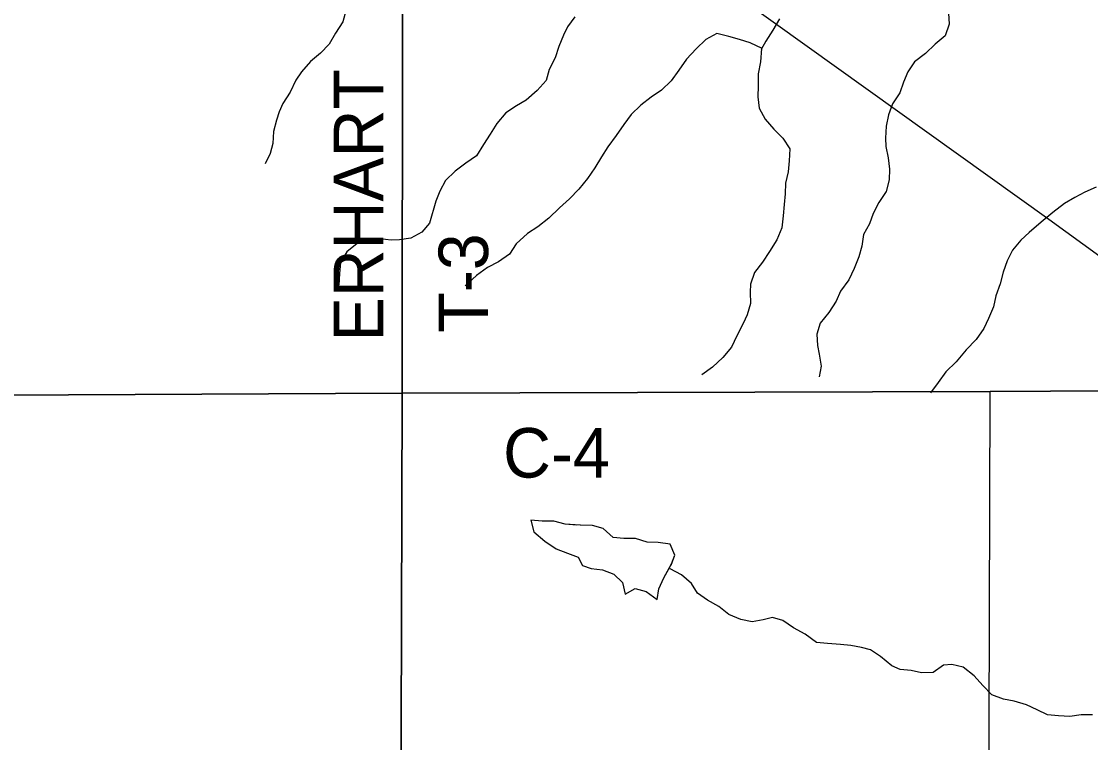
# Model space of a CAD drawing. Extents: x 1985906 to 2277390, y 930619 to 1324581.
# Drawn here: x 2110785 to 2117262, y 1140660 to 1145029 of the extents above; entities that cross this region are included whole.
import ezdxf

# ---------------------------------------------------------------- set-up
doc = ezdxf.new("R2010")
doc.units = 0
for name, color, linetype in [('GM_X_County_Road', 7, 'Continuous'), ('GM_X_County_Road_Text', 7, 'Continuous'), ('GM_X_Minor_Lake', 7, 'Continuous'), ('GM_X_Minor_River', 7, 'Continuous'), ('GM_X_Rail_Line', 7, 'Continuous'), ('GM_X_Township', 7, 'Continuous'), ('GM_X_Township_Road', 7, 'Continuous'), ('GM_X_Township_Road_Text', 7, 'Continuous')]:
    doc.layers.add(name, color=color, linetype=linetype)

msp = doc.modelspace()

# ---------------------------------------------------------------- linework, layer by layer
at = {"layer": 'GM_X_County_Road'}
for points in [[(2113092.4, 1142777.3), (2116654.7, 1142786.9), (2118848.5, 1142799.2), (2120259.1, 1142805.3), (2123319.4, 1142839.1), (2124184.9, 1142847.2)], [(2099759.2, 1142764.8), (2105186.3, 1142764.6), (2105809.5, 1142741.5), (2113092.4, 1142777.3)], [(2113088.8, 1134094.7), (2113074.8, 1137306), (2113092.4, 1142777.3)]]:
    msp.add_lwpolyline(points, dxfattribs=at)
at = {"layer": 'GM_X_Minor_Lake'}
for points in [[(2114170.4, 1141976.6), (2114080, 1141984.3), (2114011.7, 1142002.1), (2113939.5, 1142001.9), (2113871.2, 1142007.7), (2113889.6, 1141937.4), (2113956.1, 1141881.4), (2114024.5, 1141833.4), (2114092.8, 1141807.6), (2114157.2, 1141783.7), (2114183.5, 1141733.6), (2114237.7, 1141715.7), (2114306, 1141707.9), (2114374.3, 1141680), (2114426.7, 1141629.9), (2114443.1, 1141559.7), (2114503.1, 1141594), (2114569.4, 1141576.2), (2114635.9, 1141528.2), (2114647.6, 1141592.5), (2114677.4, 1141658.9), (2114724.1, 1141743.4)], [(2114148.3, 1141978.5), (2114080, 1141984.3), (2114011.7, 1142002.1), (2113939.5, 1142001.9), (2113871.2, 1142007.7), (2113889.6, 1141937.4), (2113956.1, 1141881.4), (2114024.5, 1141833.4), (2114092.8, 1141807.6), (2114157.2, 1141783.7), (2114183.5, 1141733.6), (2114237.7, 1141715.7), (2114306, 1141707.9), (2114374.3, 1141680), (2114426.7, 1141629.9), (2114443.1, 1141559.7), (2114503.1, 1141594), (2114569.4, 1141576.2), (2114635.9, 1141528.2), (2114647.6, 1141592.5), (2114677.4, 1141658.9), (2114715.2, 1141727.3)], [(2114724.1, 1141743.4), (2114743, 1141795.7), (2114714.6, 1141861.9), (2114642.3, 1141871.7), (2114576.1, 1141875.5), (2114505.8, 1141897.3), (2114435.6, 1141897.1), (2114369.3, 1141902.9), (2114308.9, 1141956.9), (2114244.6, 1141974.8), (2114170.4, 1141976.6)], [(2114721.2, 1141735.4), (2114743, 1141795.7), (2114714.6, 1141861.9), (2114642.3, 1141871.7), (2114576.1, 1141875.5), (2114505.8, 1141897.3), (2114435.6, 1141897.1), (2114369.3, 1141902.9), (2114308.9, 1141956.9), (2114244.6, 1141974.8), (2114172.3, 1141976.5)]]:
    msp.add_lwpolyline(points, dxfattribs=at)
at = {"layer": 'GM_X_Minor_River'}
for points in [[(2112751.7, 1145092.8), (2112731.9, 1145026.5), (2112688.1, 1144958.1), (2112650.2, 1144891.7), (2112596.3, 1144837.3), (2112536.3, 1144786.8), (2112482.5, 1144722.4), (2112448.6, 1144672.1), (2112412.8, 1144599.6), (2112368.9, 1144531.2), (2112347.1, 1144480.9), (2112331.3, 1144430.7), (2112313.5, 1144362.3), (2112307.8, 1144290), (2112292.1, 1144227.7), (2112262.3, 1144165.3)], [(2114138.3, 1145057.3), (2114094.5, 1144994.9), (2114068.6, 1144944.6), (2114040.8, 1144876.2), (2114019, 1144807.9), (2113983.2, 1144737.5), (2113963.5, 1144671.1), (2113909.6, 1144610.7), (2113843.6, 1144552.2), (2113783.6, 1144517.9), (2113719.6, 1144475.5), (2113665.7, 1144411), (2113625.9, 1144346.6), (2113584, 1144282.2), (2113542.2, 1144213.8), (2113478.2, 1144169.4), (2113412.2, 1144121), (2113354.2, 1144064.6), (2113320.4, 1144000.2), (2113296.6, 1143939.8), (2113257.1, 1143807.1), (2113211.2, 1143752.8), (2113145.2, 1143716.4), (2113075, 1143706.1), (2113024.8, 1143703.9), (2112956.6, 1143711.8), (2112890.4, 1143705.5), (2112820.2, 1143683.2), (2112756.3, 1143632.8), (2112718.4, 1143568.3), (2112712.7, 1143502.1), (2112709, 1143431.8)], [(2115378.4, 1145043.4), (2115336.6, 1144975), (2115294.7, 1144908.5), (2115266.9, 1144858.2)], [(2116401.6, 1145078.9), (2116405.9, 1145012.7), (2116382.1, 1144942.3), (2116320.1, 1144889.9), (2116262.2, 1144833.4), (2116196.2, 1144783), (2116154.4, 1144722.6), (2116128.6, 1144660.3), (2116106.8, 1144595.9), (2116062.9, 1144529.5), (2116037.2, 1144463.2), (2116023.4, 1144394.8), (2116019.7, 1144322.5), (2116022, 1144270.3), (2116036.3, 1144202.1), (2116044.7, 1144133.8), (2116042.9, 1144069.5), (2116023.2, 1143999.2), (2115979.4, 1143932.7), (2115945.6, 1143864.3), (2115923.8, 1143802), (2115885.9, 1143737.6), (2115876.2, 1143667.3), (2115858.5, 1143603), (2115830.7, 1143532.6), (2115796.9, 1143464.2), (2115747, 1143395.7), (2115721.2, 1143333.4), (2115677.4, 1143264.9), (2115623.5, 1143200.5), (2115603.8, 1143134.1), (2115608.1, 1143065.9), (2115618.3, 1143013.7), (2115630.7, 1142941.4), (2115619, 1142875.1)], [(2115272.9, 1144864.3), (2115200.5, 1144898.2), (2115136.2, 1144920.1), (2115069.9, 1144937.9), (2114997.6, 1144955.8), (2114931.5, 1144919.4), (2114873.6, 1144862.9), (2114813.7, 1144800.5), (2114767.8, 1144734.1), (2114722, 1144669.6), (2114662, 1144613.2), (2114600, 1144570.8), (2114538, 1144522.4), (2114480.1, 1144464), (2114434.2, 1144403.6), (2114388.4, 1144337.1), (2114338.5, 1144268.7), (2114298.7, 1144208.3), (2114258.8, 1144141.9), (2114215, 1144077.5), (2114163.1, 1144013), (2114105.2, 1143954.6), (2114045.2, 1143900.2), (2113981.3, 1143837.7), (2113913.3, 1143785.2), (2113851.3, 1143744.9), (2113783.4, 1143682.4), (2113741.5, 1143618), (2113675.5, 1143571.6), (2113609.5, 1143537.2), (2113541.5, 1143488.8), (2113473.5, 1143426.3)], [(2115267.9, 1144864.7), (2115263.2, 1144783.9), (2115249.5, 1144711.6), (2115247.8, 1144639.3), (2115246.1, 1144571), (2115254.4, 1144502.7), (2115290.8, 1144436.6), (2115343.3, 1144376.5), (2115397.7, 1144322.4), (2115440.2, 1144256.3), (2115436.5, 1144184), (2115430.7, 1144117.7), (2115415, 1144049.3), (2115411.3, 1143985.1), (2115405.6, 1143918.8), (2115399.8, 1143850.5), (2115392.2, 1143778.1), (2115362.4, 1143705.7), (2115316.6, 1143635.3), (2115274.7, 1143570.9), (2115226.8, 1143508.5), (2115203.1, 1143438.1), (2115199.3, 1143387.9), (2115201.6, 1143319.6), (2115181.9, 1143251.2), (2115158, 1143198.9), (2115120.2, 1143124.5), (2115086.4, 1143056.1), (2115034.5, 1142993.7), (2114972.6, 1142935.2), (2114906.6, 1142888.8)], [(2117295.2, 1144025.5), (2117227.1, 1143995.1), (2117167.1, 1143962.8), (2117105, 1143926.5), (2117033, 1143872), (2116963.1, 1143813.5), (2116891.1, 1143751), (2116839.2, 1143704.6), (2116789.3, 1143642.2), (2116757.5, 1143577.8), (2116731.7, 1143509.5), (2116714, 1143439.1), (2116688.2, 1143366.7), (2116674.5, 1143300.4), (2116644.7, 1143230), (2116614.9, 1143167.7), (2116569, 1143101.2), (2116509.1, 1143038.8), (2116447.2, 1142966.2), (2116385.3, 1142905.8), (2116339.5, 1142841.4), (2116291.6, 1142778.9)], [(2116489.7, 1141116.7), (2116421.4, 1141134.5), (2116371.3, 1141130.3), (2116309.3, 1141085.9), (2116237.1, 1141083.7), (2116174.8, 1141097.5), (2116108.6, 1141103.3), (2116058.3, 1141125.2), (2115989.8, 1141181.3), (2115929.4, 1141223.2), (2115875.2, 1141237.1), (2115810.9, 1141248.9), (2115746.7, 1141254.8), (2115668.4, 1141260.5), (2115602.2, 1141266.3), (2115533.7, 1141318.3), (2115463.3, 1141356.2), (2115398.9, 1141400.2), (2115334.6, 1141418.1), (2115278.5, 1141403.8), (2115212.4, 1141391.6), (2115144.1, 1141405.4), (2115071.7, 1141437.3), (2115009.3, 1141485.3), (2114940.9, 1141523.2), (2114880.5, 1141565.2), (2114844.1, 1141623.3), (2114783.7, 1141677.3), (2114715.3, 1141713.2)], [(2117273.6, 1140828.1), (2117205.4, 1140827.8), (2117137.2, 1140819.6), (2117066.9, 1140823.3), (2117000.7, 1140829.1), (2116938.3, 1140859.1), (2116874, 1140889), (2116799.7, 1140910.8), (2116735.4, 1140922.7), (2116665, 1140950.6), (2116608.6, 1141006.6), (2116556.2, 1141064.7), (2116489.7, 1141116.7)]]:
    msp.add_lwpolyline(points, dxfattribs=at)
at = {"layer": 'GM_X_Rail_Line'}
msp.add_lwpolyline([(2109964.6, 1148874.9), (2111562.6, 1147729.8), (2113121.6, 1146613.1), (2115354.1, 1145016.1), (2117010.2, 1143831), (2117318.4, 1143607.8)], dxfattribs=at)
at = {"layer": 'GM_X_Township'}
for points in [[(2106159.1, 1165987.2), (2113358.2, 1166007.9), (2113356.1, 1165889.3), (2113339.2, 1164894), (2113290.5, 1162037.2), (2113263, 1160423.4), (2113243.3, 1159266.8), (2113217.3, 1157737.8), (2113184.2, 1154330.1), (2113157.3, 1151039.7), (2113152.8, 1150701.9), (2113139.2, 1149689.6), (2113093.1, 1145116.7), (2113092.4, 1142777.3), (2105809.5, 1142741.5)], [(2139795.7, 1143054.9), (2135286.4, 1142976.3), (2133817.9, 1142950.4), (2132555.8, 1142928.1), (2131997.1, 1142931), (2131452.7, 1142910.2), (2129353.4, 1142890), (2127335.9, 1142876.6), (2123319.4, 1142839.1), (2120259.1, 1142805.3), (2118848.4, 1142799.2), (2116654.7, 1142786.8), (2113092.4, 1142777.3), (2113093.1, 1145116.7), (2113139.2, 1149689.6)], [(2113013.5, 1120998.4), (2113067, 1126004.1), (2113071.5, 1129190.6), (2113088.8, 1134094.8), (2113074.8, 1137306), (2113092.4, 1142777.3), (2116654.7, 1142786.8), (2118848.4, 1142799.2), (2120259.1, 1142805.3), (2123319.4, 1142839.1), (2127335.9, 1142876.6), (2129353.4, 1142890), (2131452.7, 1142910.2), (2131997.1, 1142931), (2132555.8, 1142928.1), (2133817.9, 1142950.4), (2135286.4, 1142976.3), (2139795.7, 1143054.9), (2139821.3, 1140616.2), (2139800.5, 1129668.5), (2139793.2, 1125847.3), (2139773.1, 1121339.9)], [(2105809.5, 1142741.5), (2113092.4, 1142777.3), (2113074.8, 1137306), (2113088.8, 1134094.8), (2113071.5, 1129190.6), (2113067, 1126004.1), (2113013.5, 1120998.4), (2113014.5, 1120666.5), (2112984.3, 1116083.4), (2104968.7, 1116054)]]:
    msp.add_lwpolyline(points, dxfattribs=at)
at = {"layer": 'GM_X_Township_Road'}
for points in [[(2113092.4, 1142777.3), (2113093.1, 1145116.7), (2113132.5, 1149021.7)], [(2116629.6, 1134096.4), (2116634.3, 1135817.4), (2116637.3, 1137343.9), (2116654.7, 1142786.9)]]:
    msp.add_lwpolyline(points, dxfattribs=at)

# ---------------------------------------------------------------- texts
at = {"layer": 'GM_X_County_Road_Text'}
msp.add_text('C-4', height=300, rotation=0.00001, dxfattribs=at).set_placement((2113703.3, 1142265.7))
at = {"layer": 'GM_X_Township_Road_Text'}
for s, p in [('ERHART', (2112977.4, 1143090.5)), ('T-3', (2113612.4, 1143143.3))]:
    msp.add_text(s, height=300, rotation=90, dxfattribs=at).set_placement(p)

doc.saveas('drawing.dxf')
